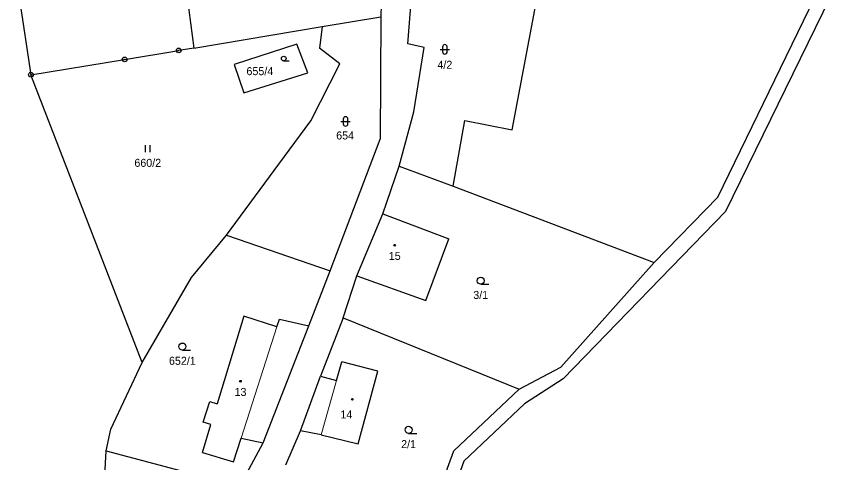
# Model space of a CAD drawing. Extents: x -739410 to -735662, y -942282 to -940043.
# Drawn here: x -738116.2 to -737941.4, y -941824.2 to -941729.3 of the extents above; entities that cross this region are included whole.
import ezdxf
from ezdxf.enums import TextEntityAlignment as Align

# ---------------------------------------------------------------- set-up
doc = ezdxf.new("R2010")
doc.units = 0
doc.header["$LTSCALE"] = 0.68
for name, color, linetype, lineweight in [('1', 7, 'Continuous', 25), ('3', 7, 'Continuous', 25), ('4', 7, 'Continuous', 13), ('5', 7, 'Continuous', 25), ('8', 7, 'Continuous', 25)]:
    doc.layers.add(name, color=color, linetype=linetype, lineweight=lineweight)
doc.layers.add('2', color=7, linetype='Continuous')

msp = doc.modelspace()

# ---------------------------------------------------------------- linework, layer by layer
at = {"layer": '1'}
for p, q in [((-738083.31, -941700.23), (-738078.53, -941736.07)), ((-738033.05, -941735.17), (-738031.16, -941711.52)), ((-737967.24, -941767.79), (-737944.1, -941720.02)), ((-738116.2, -941721.4), (-738113.13, -941741.73)), ((-737941.37, -941721.17), (-737965.58, -941770.84)), ((-738010.91, -941753.43), (-738005.44, -941724.42)), ((-738038.72, -941726.71), (-738038.83, -941729.42)), ((-738051.27, -941731.5), (-738038.83, -941729.42)), ((-738038.83, -941729.42), (-738038.94, -941755.43)), ((-738078.53, -941736.07), (-738051.27, -941731.5)), ((-738051.27, -941731.5), (-738051.82, -941736.11)), ((-738056.67, -941735.22), (-738069.93, -941739.54)), ((-738054.32, -941741.36), (-738056.67, -941735.22)), ((-738029.6, -941735.94), (-738033.05, -941735.17)), ((-738093.23, -941738.47), (-738081.74, -941736.56)), ((-738078.53, -941736.07), (-738081.74, -941736.56)), ((-738047.5, -941739.44), (-738051.82, -941736.11)), ((-738031.77, -941749.63), (-738029.6, -941735.94)), ((-738113.13, -941741.73), (-738093.23, -941738.47)), ((-738069.93, -941739.54), (-738067.88, -941745.6)), ((-738053.67, -941751.53), (-738047.5, -941739.44)), ((-738089.51, -941802.91), (-738113.13, -941741.73)), ((-738067.88, -941745.6), (-738054.32, -941741.36)), ((-738034.88, -941761.19), (-738031.77, -941749.63)), ((-738023.41, -941765.44), (-738020.96, -941751.47)), ((-738020.96, -941751.47), (-738010.91, -941753.43)), ((-738060.49, -941760.78), (-738053.67, -941751.53)), ((-738049.57, -941783.41), (-738038.94, -941755.43)), ((-738071.57, -941775.87), (-738060.49, -941760.78)), ((-738038.39, -941771.3), (-738034.88, -941761.19)), ((-738034.88, -941761.19), (-738023.41, -941765.44)), ((-738023.41, -941765.44), (-737980.72, -941781.66)), ((-737980.72, -941781.66), (-737967.24, -941767.79)), ((-738043.88, -941784.48), (-738038.39, -941771.3)), ((-738038.39, -941771.3), (-738024.37, -941776.62)), ((-737965.58, -941770.84), (-738000.07, -941806.36)), ((-738078.99, -941784.82), (-738071.57, -941775.87)), ((-738071.57, -941775.87), (-738049.57, -941783.41)), ((-738029.27, -941789.72), (-738024.37, -941776.62)), ((-738000.54, -941803.92), (-737980.72, -941781.66)), ((-738054.12, -941795.13), (-738049.57, -941783.41)), ((-738046.83, -941793.44), (-738043.88, -941784.48)), ((-738043.88, -941784.48), (-738029.27, -941789.72)), ((-738089.51, -941802.91), (-738078.99, -941784.82)), ((-738067.92, -941793.07), (-738073.54, -941811.69)), ((-738060.88, -941795.33), (-738067.92, -941793.07)), ((-738046.83, -941793.44), (-738051.63, -941805.84)), ((-738046.83, -941793.44), (-738009.42, -941808.6)), ((-738063.77, -941820), (-738054.12, -941795.13)), ((-738060.88, -941795.33), (-738060.35, -941793.67)), ((-738060.35, -941793.67), (-738054.12, -941795.13)), ((-738096.12, -941817.06), (-738089.51, -941802.91)), ((-738048.21, -941806.71), (-738047.09, -941802.77)), ((-738039.46, -941804.75), (-738047.09, -941802.77)), ((-738009.42, -941808.6), (-738000.54, -941803.92)), ((-738043.64, -941820.18), (-738039.46, -941804.75)), ((-738055.9, -941817.46), (-738051.63, -941805.84)), ((-738051.63, -941805.84), (-738048.21, -941806.71)), ((-738000.07, -941806.36), (-738008.26, -941811.73)), ((-738023.33, -941821.72), (-738009.42, -941808.6)), ((-738076.51, -941815.58), (-738075.16, -941811.19)), ((-738075.16, -941811.19), (-738073.54, -941811.69)), ((-738008.26, -941811.73), (-738021.15, -941823.92)), ((-738076.71, -941822.01), (-738074.89, -941816.08)), ((-738074.89, -941816.08), (-738076.51, -941815.58)), ((-738097.15, -941821.66), (-738096.12, -941817.06)), ((-738058.97, -941824.69), (-738055.9, -941817.46)), ((-738051.48, -941818.26), (-738055.9, -941817.46)), ((-738070.1, -941824.04), (-738068.48, -941818.99)), ((-738068.48, -941818.99), (-738063.77, -941820)), ((-738051.48, -941818.26), (-738043.64, -941820.18)), ((-738068.76, -941829.21), (-738063.77, -941820)), ((-738098.01, -941838.56), (-738097.15, -941821.66)), ((-738097.15, -941821.66), (-738068.76, -941829.21)), ((-738076.71, -941822.01), (-738070.1, -941824.04)), ((-738031.03, -941842.59), (-738023.33, -941821.72)), ((-738021.15, -941823.92), (-738032.18, -941853.87))]:
    msp.add_line(p, q, dxfattribs=at)
at = {"layer": '3'}
for p, q in [((-738026.201, -941736.341), (-738024.199, -941736.341)), ((-738025.701, -941735.841), (-738025.701, -941736.842)), ((-738024.699, -941736.842), (-738024.699, -941735.841)), ((-738059.435, -941738.79), (-738058.263, -941738.79)), ((-738046.801, -941751.171), (-738046.801, -941752.172)), ((-738045.799, -941752.172), (-738045.799, -941751.171)), ((-738047.301, -941751.671), (-738045.299, -941751.671)), ((-738088.821, -941758.19), (-738088.821, -941756.69)), ((-738087.82, -941758.19), (-738087.82, -941756.69)), ((-738017.583, -941786.27), (-738015.833, -941786.27)), ((-738080.953, -941800.27), (-738079.203, -941800.27)), ((-738032.903, -941817.98), (-738031.153, -941817.98))]:
    msp.add_line(p, q, dxfattribs=at)
for centre, radius in [((-738059.4352, -941738.2874), 0.5025), ((-738017.5829, -941785.5198), 0.75), ((-738080.9529, -941799.5198), 0.75), ((-738032.9029, -941817.2298), 0.75)]:
    msp.add_circle(centre, radius, dxfattribs=at)
for centre, start, end in [((-738025.2, -941735.8409), 0, 180), ((-738025.2, -941736.8409), 180, 359.98789), ((-738046.3, -941751.1709), 0, 180), ((-738046.3, -941752.1709), 180, 359.98789)]:
    msp.add_arc(centre, 0.5, start, end, dxfattribs=at)
at = {"layer": '4'}
for p, q in [((-738068.48, -941818.99), (-738060.88, -941795.33)), ((-738051.48, -941818.26), (-738048.21, -941806.71))]:
    msp.add_line(p, q, dxfattribs=at)
at = {"layer": '5'}
for centre in [(-738035.8568, -941777.9692), (-738068.6168, -941806.8892), (-738044.8468, -941810.7392)]:
    msp.add_circle(centre, 0.175, dxfattribs=at)
at = {"layer": '8'}
for centre, radius in [((-738081.74, -941736.5599), 0.5), ((-738081.74, -941736.5599), 0.0303), ((-738093.23, -941738.4699), 0.5), ((-738093.23, -941738.4699), 0.0303), ((-738113.13, -941741.7299), 0.5), ((-738113.13, -941741.7299), 0.0303)]:
    msp.add_circle(centre, radius, dxfattribs=at)

# ---------------------------------------------------------------- texts
at = {"layer": '2'}
for s, p in [('4/2', (-738025.2, -941740.465)), ('655/4', (-738064.5, -941741.825)), ('654', (-738046.389, -941755.495)), ('660/2', (-738088.31, -941761.315)), ('15', (-738035.849, -941781.095)), ('3/1', (-738017.59, -941789.395)), ('652/1', (-738080.96, -941803.395)), ('13', (-738068.609, -941810.015)), ('14', (-738046.119, -941814.805)), ('2/1', (-738032.91, -941821.105))]:
    msp.add_text(s, height=1.7, dxfattribs=at).set_placement(p, align=Align.CENTER)

doc.saveas('drawing.dxf')
